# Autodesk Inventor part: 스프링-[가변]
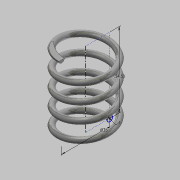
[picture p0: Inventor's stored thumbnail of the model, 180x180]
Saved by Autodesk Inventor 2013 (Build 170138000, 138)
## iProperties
Created: 2015-03
Part Number: 스프링-[가변]
Material: 강철, 탄소
Document SubType Name: Modeling
Designer: kb146
Density: 7.87 g/cm^3
Mass: 47.9804 g
Surface Area: 62.0042 cm^2
Volume: 6.09663 cm^3
Author: kb146
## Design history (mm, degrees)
sketch "스케치1"
  geometry: L1 (0, 0)-(17.5, 0); L2 (17.5, 0)-(17.5, 43.5); L3 (17.5, 43.5)-(0, 43.5); L4 (0, 43.5)-(0, 0); C1 r 2 at (17.5, 0); 1 further point
  constraints: 8 end point, 2 coincident, 2 parallel, 1 centre point, 1 horizontal, 1 perpendicular
  dimensions: "d0" = 4 diameter of C1; "d2" = 35 diameter of L2 L4; "d3" = 43.5 distance between parallel lines of L1 L3 (derived)
feature "코일1" pitch "d4" = 10; turns "d6" = 4.5; dims "d5" = 43.5 (= d3), "d7" = 0, angle "d8" = 90 deg, angle "d9" = 90 deg, "d10" = 0, "d11" = 0
sketch "스케치2"
  geometry: L1 (0, 19.5)-(0, 15.5) reference; 1 further point
  constraints: 1 vertical alignment
extrude "돌출1" cut sketch "스케치2" stored distance "d12" = 10; taper "d13" = 0 deg
node "작업 평면1"
sketch "스케치3"
  geometry: L1 (37, 0)-(33, 0) reference; 1 further point
  constraints: 1 horizontal alignment
extrude "돌출2" cut sketch "스케치3" stored distance "d15" = 10; taper "d16" = 0 deg
node "솔리드1"
node "절단 모서리 투영1"
node "절단 모서리 투영2"
other parameters: "d14" = 180 deg
